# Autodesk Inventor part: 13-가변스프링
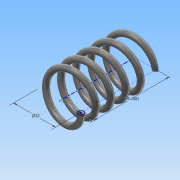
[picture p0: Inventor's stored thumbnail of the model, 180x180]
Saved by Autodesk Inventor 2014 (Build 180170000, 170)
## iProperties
Created: 2015-09
Part Number: 13-가변스프링
Material: 강철, 탄소
Document SubType Name: Modeling
Designer: study
Density: 7.87 g/cm^3
Appearance: 반연마
Mass: 18.9136 g
Surface Area: 32.5767 cm^2
Volume: 2.40325 cm^3
Author: study
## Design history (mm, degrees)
sketch "스케치1"
  geometry: L1 (0, 0)-(11, 0); L2 (11, 0)-(11, 39.258); L3 (11, 39.258)-(0, 39.258); L4 (0, 39.258)-(0, 0); C1 r 1.5 at (11, 0); 1 further point
  constraints: 8 end point, 2 coincident, 2 parallel, 1 centre point, 1 horizontal, 1 perpendicular
  dimensions: "d0" = 22 diameter of L2 L4; "d1" = 39.25829 distance between parallel lines of L1 L3 (derived); "d2" = 3 diameter of C1
feature "코일1" sketch "스케치1" pitch "d3" = 10; turns "d5" = 5; dims "d4" = 39.25829 (= d1), "d6" = 0, angle "d7" = 90 deg, angle "d8" = 90 deg, "d9" = 0, "d10" = 0
node "작업 평면1"
sketch "스케치2"
  geometry: L1 (-12.5, 0)-(-9.5, 0) reference; 1 further point
  constraints: 1 horizontal alignment
extrude "돌출1" cut sketch "스케치2" stored distance "d12" = 10; taper "d13" = 0 deg
node "작업 평면2"
sketch "스케치3"
  geometry: L1 (-9.5, 0)-(-12.5, 0) reference; 1 further point
  constraints: 1 horizontal alignment
extrude "돌출2" cut sketch "스케치3" stored distance "d15" = 10; taper "d16" = 0 deg
node "솔리드1"
node "절단 모서리 투영1"
node "절단 모서리 투영2"
other parameters: "d11" = 0, "d14" = 39.25829 (= d1)
